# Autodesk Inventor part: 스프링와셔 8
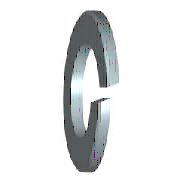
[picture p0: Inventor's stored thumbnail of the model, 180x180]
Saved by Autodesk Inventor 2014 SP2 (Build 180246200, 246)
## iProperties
IsCustomPart: 1
Created: 2012-02
Part Number: 스프링와셔 8
Material: 강철, 연강
Description: 스프링 잠금 와셔
Document SubType Name: Modeling
Standard: KS B 1324
Designer: mduedu
Standards Organization: KS
Language: ko-KR
Size Designation: 번호 3 - 8
Categories: <MemberInstance><Categories><Category DisplayName="조임쇠" InternalName="e4da775c-781d-43d5-af7c-5136215cf5a6" Mnemonic="FSTN"><Category DisplayName="와셔" InternalN
Density: 1 g/cm^3
Appearance: 파란색 - 벽 페인트 - 광택
Author: mduedu
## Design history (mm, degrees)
sketch "스케치1"
  geometry: C1 r 7.4 at (0, 0); C2 r 4.1 at (0, 0); 1 further point
  constraints: 2 centre point, 2 coincident
  dimensions: "d0" = 8.2 diameter of C2 (= SD1); "d1" = 14.8 diameter of C1 (= SD2)
extrude "본체" new body sketch "스케치1" distance "d2" = 2.5 (= SD); taper "d3" = 0 deg
sketch "스케치2"
  geometry: L1 (0, -4.1)-(0, 4.1) reference; L2 (2.5, 7.4)-(2.5, -7.4) reference; L3 (-1.2, 0)-(7.2, 0) reference; L4 (0, -0.5)-(2.5, 0.41); L5 (0, 0.5)-(2.5, 1.41)
  constraints: 4 end point, 4 point on line, 1 parallel
  dimensions: "d4" = 0.5 distance from line of L3 L4.start (= 0.2 x SD); "d5" = 0.5 distance from line of L3 L5.start (= 0.2 x SD); "d6" = 70 deg angle of L2 L4 (= FAWI)
extrude "절단부" cut sketch "스케치2" stored distance "d7" = 2.5 (= SD); taper "d8" = 0 deg
workaxis "Work Axis1"
workplane "Work Plane1"
body "Solid1"
other parameters: "SD1" = 8.2 [user parameter; used in 1 equation term], "SD2" = 14.8 [user parameter; used in 1 equation term], "SD" = 2.5 [user parameter; used in 4 equation terms], "FAWI" = 70 deg [user parameter; used in 1 equation term], "d9" = 0, "d10" = 0, "d11" = 0, "d12" = 0, "SDI" = 3.3 [user parameter], "NND" = 8 [user parameter]
